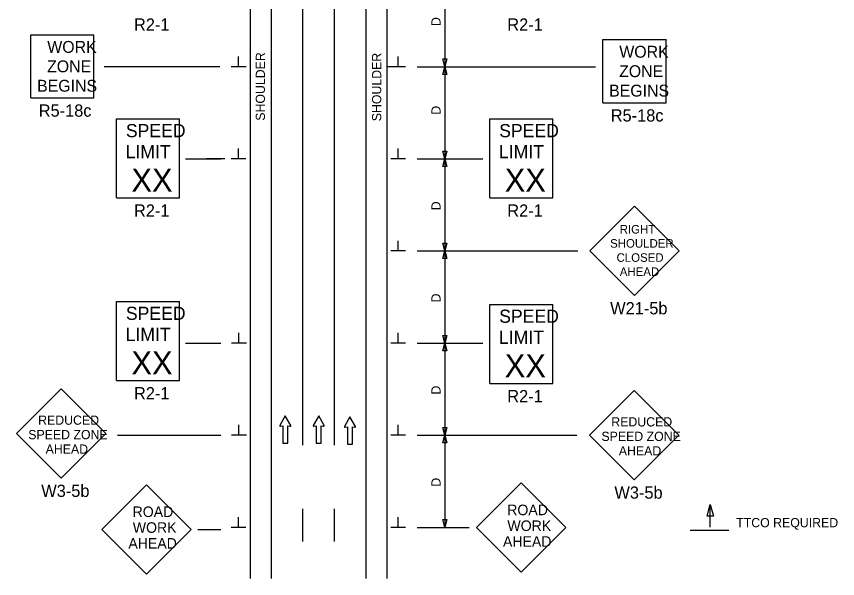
# Model space of a CAD drawing. Extents: x 16741 to 18479, y 6916 to 8211.
# Drawn here: x 16743 to 17367, y 7354 to 7781 of the extents above; entities that cross this region are included whole.
import ezdxf

# ---------------------------------------------------------------- set-up
doc = ezdxf.new("R2010")
doc.units = 0
for name, color, linetype in [('ALI_LEGAL_EX', 7, 'Continuous'), ('MT_SCRATCH_LEVEL_E', 7, 'Continuous'), ('PAVT_EDGE_EX', 7, 'Continuous'), ('TRAFFIC_SIGNS_PR', 7, 'Continuous'), ('TYPICAL_TEXT_DIMEN_PR', 7, 'Continuous')]:
    doc.layers.add(name, color=color, linetype=linetype)

msp = doc.modelspace()

# ---------------------------------------------------------------- linework, layer by layer
at = {"layer": 'ALI_LEGAL_EX'}
for p, q in [((16960.92, 8208.99), (16960.92, 7455.58)), ((16984.92, 8208.99), (16984.92, 7455.58))]:
    msp.add_line(p, q, dxfattribs=at)
for points in [[(16960.92, 7707.36), (16960.92, 7682.36)], [(16984.92, 7707.36), (16984.92, 7682.36)], [(16960.92, 7607.36), (16960.92, 7582.36)], [(16984.92, 7607.36), (16984.92, 7582.36)], [(16960.92, 7507.36), (16960.92, 7482.36)], [(16984.92, 7507.36), (16984.92, 7482.36)], [(16960.92, 7407.36), (16960.92, 7382.36)], [(16984.92, 7407.36), (16984.92, 7382.36)]]:
    msp.add_lwpolyline(points, dxfattribs=at)
at = {"layer": 'MT_SCRATCH_LEVEL_E'}
for p, q in [((16947.72, 7477.89), (16943.61, 7470.65)), ((16947.72, 7477.89), (16943.61, 7470.65)), ((16951.87, 7470.65), (16947.72, 7477.89)), ((16951.87, 7470.65), (16947.72, 7477.89)), ((16973.15, 7477.89), (16969.04, 7470.65)), ((16973.15, 7477.89), (16969.04, 7470.65)), ((16977.3, 7470.65), (16973.15, 7477.89)), ((16977.3, 7470.65), (16973.15, 7477.89)), ((16996.85, 7477.15), (16992.74, 7469.91)), ((16996.85, 7477.15), (16992.74, 7469.91)), ((17001, 7469.91), (16996.85, 7477.15)), ((17001, 7469.91), (16996.85, 7477.15)), ((16944.1, 7469.96), (16945.87, 7470.28)), ((16944.1, 7469.96), (16945.87, 7470.28)), ((16945.87, 7470.28), (16945.87, 7457.02)), ((16945.87, 7470.28), (16945.87, 7457.02)), ((16949.61, 7457.02), (16949.61, 7470.28)), ((16949.61, 7470.28), (16951.39, 7469.96)), ((16949.61, 7457.02), (16949.61, 7470.28)), ((16949.61, 7470.28), (16951.39, 7469.96)), ((16969.52, 7469.96), (16971.3, 7470.28)), ((16969.52, 7469.96), (16971.3, 7470.28)), ((16971.3, 7470.28), (16971.3, 7457.02)), ((16971.3, 7470.28), (16971.3, 7457.02)), ((16975.04, 7457.02), (16975.04, 7470.28)), ((16975.04, 7470.28), (16976.82, 7469.96)), ((16975.04, 7457.02), (16975.04, 7470.28)), ((16975.04, 7470.28), (16976.82, 7469.96)), ((16993.22, 7469.23), (16995, 7469.55)), ((16993.22, 7469.23), (16995, 7469.55)), ((16995, 7469.55), (16995, 7456.29)), ((16995, 7469.55), (16995, 7456.29)), ((16998.74, 7456.29), (16998.74, 7469.55)), ((16998.74, 7469.55), (17000.52, 7469.23)), ((16998.74, 7456.29), (16998.74, 7469.55)), ((16998.74, 7469.55), (17000.52, 7469.23)), ((16945.87, 7457.02), (16949.61, 7457.02)), ((16945.87, 7457.02), (16949.61, 7457.02)), ((16971.3, 7457.02), (16975.04, 7457.02)), ((16971.3, 7457.02), (16975.04, 7457.02)), ((16995, 7456.29), (16998.74, 7456.29)), ((16995, 7456.29), (16998.74, 7456.29))]:
    msp.add_line(p, q, dxfattribs=at)
for centre, start, end in [((16944.02, 7470.42), 150.42484, 279.96381), ((16944.02, 7470.42), 150.42484, 279.96381), ((16951.46, 7470.42), 260.03619, 29.77312), ((16951.46, 7470.42), 260.03619, 29.77312), ((16969.45, 7470.42), 150.42484, 279.96381), ((16969.45, 7470.42), 150.42484, 279.96381), ((16976.89, 7470.42), 260.03619, 29.77312), ((16976.89, 7470.42), 260.03619, 29.77312), ((16993.15, 7469.69), 150.42484, 279.96381), ((16993.15, 7469.69), 150.42484, 279.96381), ((17000.59, 7469.69), 260.03619, 29.77312), ((17000.59, 7469.69), 260.03619, 29.77312)]:
    msp.add_arc(centre, 0.463, start, end, dxfattribs=at)
at = {"layer": 'PAVT_EDGE_EX'}
for p, q in [((16920.92, 8208.99), (16920.92, 7354.26)), ((16936.92, 8208.99), (16936.92, 7354.26)), ((17008.92, 8208.99), (17008.92, 7354.26)), ((17024.92, 8208.99), (17024.92, 7354.26)), ((17028.22, 7743.18), (17024.92, 7743.18))]:
    msp.add_line(p, q, dxfattribs=at)
at = {"layer": 'TRAFFIC_SIGNS_PR'}
for p, q in [((16754.36, 7719.49), (16754.36, 7767.49)), ((16754.36, 7767.49), (16802.36, 7767.49)), ((16802.36, 7719.49), (16802.36, 7767.49)), ((17189.05, 7715.8), (17189.05, 7763.8)), ((17189.05, 7763.8), (17237.05, 7763.8)), ((17237.05, 7715.8), (17237.05, 7763.8)), ((16754.36, 7719.49), (16802.36, 7719.49)), ((17189.05, 7715.8), (17237.05, 7715.8)), ((16819.42, 7703.53), (16867.42, 7703.53)), ((16819.42, 7643.53), (16819.42, 7703.53)), ((16867.42, 7643.53), (16867.42, 7703.53)), ((17103.1, 7703.53), (17151.1, 7703.53)), ((17103.1, 7643.53), (17103.1, 7703.53)), ((17151.1, 7643.53), (17151.1, 7703.53)), ((16819.42, 7643.53), (16867.42, 7643.53)), ((17103.1, 7643.53), (17151.1, 7643.53)), ((17213.17, 7637.2), (17179.23, 7603.26)), ((17247.11, 7603.26), (17213.17, 7637.2)), ((17179.23, 7603.26), (17213.17, 7569.31)), ((17213.17, 7569.31), (17247.11, 7603.26)), ((16819.42, 7564.71), (16867.42, 7564.71)), ((16819.42, 7504.71), (16819.42, 7564.71)), ((16867.42, 7504.71), (16867.42, 7564.71)), ((17103.1, 7562.52), (17151.1, 7562.52)), ((17103.1, 7502.52), (17103.1, 7562.52)), ((17151.1, 7502.52), (17151.1, 7562.52)), ((16819.42, 7504.71), (16867.42, 7504.71)), ((17103.1, 7502.52), (17151.1, 7502.52)), ((16777.36, 7498.45), (16743.42, 7464.51)), ((16811.3, 7464.51), (16777.36, 7498.45)), ((17212.9, 7497.14), (17178.96, 7463.2)), ((17246.84, 7463.2), (17212.9, 7497.14)), ((16743.42, 7464.51), (16777.36, 7430.57)), ((16777.36, 7430.57), (16811.3, 7464.51)), ((17178.96, 7463.2), (17212.9, 7429.26)), ((17212.9, 7429.26), (17246.84, 7463.2)), ((17126.96, 7426.95), (17093.02, 7393.01)), ((17160.9, 7393.01), (17126.96, 7426.95)), ((16842.28, 7425.55), (16808.34, 7391.61)), ((16876.22, 7391.61), (16842.28, 7425.55)), ((16808.34, 7391.61), (16842.28, 7357.67)), ((16842.28, 7357.67), (16876.22, 7391.61)), ((17093.02, 7393.01), (17126.96, 7359.07)), ((17126.96, 7359.07), (17160.9, 7393.01))]:
    msp.add_line(p, q, dxfattribs=at)
at = {"layer": 'TYPICAL_TEXT_DIMEN_PR'}
for p, q in [((17068.92, 7813.18), (17068.92, 7743.18)), ((16912.29, 7743.18), (16912.29, 7750.97)), ((17033.54, 7743.18), (17033.54, 7750.97)), ((17068.92, 7743.18), (17067.35, 7749.04)), ((17067.35, 7749.04), (17068.92, 7749.04)), ((17068.92, 7743.18), (17067.35, 7749.04)), ((17067.35, 7749.04), (17068.92, 7749.04)), ((17068.92, 7749.04), (17070.49, 7749.04)), ((17070.49, 7749.04), (17068.92, 7743.18)), ((17068.92, 7749.04), (17070.49, 7749.04)), ((17070.49, 7749.04), (17068.92, 7743.18)), ((16897.92, 7743.18), (16810.2, 7743.18)), ((16912.29, 7743.18), (16906.67, 7743.18)), ((16917.92, 7743.18), (16912.29, 7743.18)), ((17033.54, 7743.18), (17027.92, 7743.18)), ((17039.17, 7743.18), (17033.54, 7743.18)), ((17047.92, 7743.18), (17183.51, 7743.18)), ((17067.35, 7737.32), (17068.92, 7743.18)), ((17068.92, 7743.18), (17068.92, 7673.18)), ((17068.92, 7743.18), (17070.49, 7737.32)), ((17068.92, 7737.32), (17067.35, 7737.32)), ((17070.49, 7737.32), (17068.92, 7737.32)), ((16912.13, 7673.18), (16912.13, 7680.97)), ((17033.54, 7673.18), (17033.54, 7680.97)), ((17068.92, 7673.18), (17067.35, 7679.04)), ((17067.35, 7679.04), (17068.92, 7679.04)), ((17068.92, 7679.04), (17070.49, 7679.04)), ((17070.49, 7679.04), (17068.92, 7673.18)), ((16871.92, 7673.18), (16898.82, 7673.18)), ((16901.7, 7673.14), (16887.9, 7673.14)), ((16912.13, 7673.18), (16906.51, 7673.18)), ((16917.76, 7673.18), (16912.13, 7673.18)), ((17033.54, 7673.18), (17027.92, 7673.18)), ((17039.17, 7673.18), (17033.54, 7673.18)), ((17047.92, 7673.18), (17097.97, 7673.18)), ((17067.35, 7667.32), (17068.92, 7673.18)), ((17068.92, 7673.18), (17068.92, 7603.18)), ((17068.92, 7673.18), (17070.49, 7667.32)), ((17068.92, 7667.32), (17067.35, 7667.32)), ((17070.49, 7667.32), (17068.92, 7667.32)), ((17033.54, 7603.18), (17033.54, 7610.97)), ((17068.92, 7603.18), (17067.35, 7609.04)), ((17067.35, 7609.04), (17068.92, 7609.04)), ((17068.92, 7609.04), (17070.49, 7609.04)), ((17070.49, 7609.04), (17068.92, 7603.18)), ((17033.54, 7603.18), (17027.92, 7603.18)), ((17039.17, 7603.18), (17033.54, 7603.18)), ((17047.92, 7603.18), (17169.97, 7603.18)), ((17067.35, 7597.32), (17068.92, 7603.18)), ((17068.92, 7603.18), (17068.92, 7533.18)), ((17068.92, 7603.18), (17070.49, 7597.32)), ((17068.92, 7597.32), (17067.35, 7597.32)), ((17070.49, 7597.32), (17068.92, 7597.32)), ((16912.52, 7533.18), (16912.52, 7540.97)), ((17033.54, 7533.18), (17033.54, 7540.97)), ((17068.92, 7533.18), (17067.35, 7539.04)), ((17067.35, 7539.04), (17068.92, 7539.04)), ((17068.92, 7539.04), (17070.49, 7539.04)), ((17070.49, 7539.04), (17068.92, 7533.18)), ((16871.92, 7533.18), (16898.82, 7533.18)), ((16912.52, 7533.18), (16906.89, 7533.18)), ((16918.14, 7533.18), (16912.52, 7533.18)), ((17033.54, 7533.18), (17027.92, 7533.18)), ((17039.17, 7533.18), (17033.54, 7533.18)), ((17047.92, 7533.18), (17097.97, 7533.18)), ((17067.35, 7527.32), (17068.92, 7533.18)), ((17068.92, 7533.18), (17068.92, 7463.18)), ((17068.92, 7533.18), (17070.49, 7527.32)), ((17068.92, 7527.32), (17067.35, 7527.32)), ((17070.49, 7527.32), (17068.92, 7527.32)), ((16912.52, 7463.18), (16912.52, 7470.97)), ((17033.54, 7463.18), (17033.54, 7470.97)), ((16820.27, 7463.18), (16898.82, 7463.18)), ((16912.52, 7463.18), (16906.89, 7463.18)), ((16918.14, 7463.18), (16912.52, 7463.18)), ((17033.54, 7463.18), (17027.92, 7463.18)), ((17039.17, 7463.18), (17033.54, 7463.18)), ((17047.92, 7463.18), (17169.32, 7463.18)), ((17068.92, 7463.18), (17067.35, 7469.04)), ((17067.35, 7469.04), (17068.92, 7469.04)), ((17067.35, 7457.32), (17068.92, 7463.18)), ((17068.92, 7469.04), (17070.49, 7469.04)), ((17070.49, 7469.04), (17068.92, 7463.18)), ((17068.92, 7463.18), (17068.92, 7393.18)), ((17068.92, 7463.18), (17070.49, 7457.32)), ((17068.92, 7457.32), (17067.35, 7457.32)), ((17070.49, 7457.32), (17068.92, 7457.32)), ((17268.34, 7401.67), (17270.69, 7410.46)), ((17270.69, 7393.34), (17270.69, 7410.46)), ((17270.69, 7410.46), (17273.05, 7401.67)), ((16912.22, 7393.18), (16912.22, 7400.97)), ((17033.54, 7393.18), (17033.54, 7400.97)), ((17270.69, 7401.67), (17268.34, 7401.67)), ((17273.05, 7401.67), (17270.69, 7401.67)), ((17068.92, 7393.18), (17067.35, 7399.04)), ((17067.35, 7399.04), (17068.92, 7399.04)), ((17068.92, 7399.04), (17070.49, 7399.04)), ((17070.49, 7399.04), (17068.92, 7393.18)), ((16881.24, 7391.57), (16898.82, 7391.57)), ((16912.22, 7393.18), (16906.6, 7393.18)), ((16917.85, 7393.18), (16912.22, 7393.18)), ((17033.54, 7393.18), (17027.92, 7393.18)), ((17039.17, 7393.18), (17033.54, 7393.18)), ((17047.92, 7393.18), (17087.38, 7393.18)), ((17284.87, 7390.84), (17255.43, 7390.84))]:
    msp.add_line(p, q, dxfattribs=at)

# ---------------------------------------------------------------- texts
at = {"layer": 'TRAFFIC_SIGNS_PR'}
for s, height, p in [('R2-1', 9.3, (16832.76, 7770.56)), ('R2-1', 9.3, (17116.44, 7770.56)), ('WORK', 9.021, (16766.86, 7753.7)), ('WORK', 9.021, (17201.55, 7750.01)), ('ZONE', 9.021, (16766.71, 7738.94)), ('ZONE', 9.021, (17201.4, 7735.24)), ('BEGINS', 9.021, (16759.12, 7724.18)), ('BEGINS', 9.021, (17193.81, 7720.48)), ('R5-18c', 9.3, (16760.38, 7705.19)), ('R5-18c', 9.3, (17195.06, 7701.5)), ('SPEED', 10, (16826.62, 7689.61)), ('SPEED', 10, (17110.3, 7689.61)), ('LIMIT', 10, (16826.42, 7673.61)), ('LIMIT', 10, (17110.1, 7673.61)), ('XX', 17.538, (16830.81, 7648.23)), ('XX', 17.538, (17114.49, 7648.23)), ('R2-1', 9.3, (16832.76, 7629.24)), ('R2-1', 9.3, (17116.44, 7629.24)), ('RIGHT', 6.5, (17201.84, 7616.42)), ('SHOULDER', 6.5, (17194.57, 7605.67)), ('CLOSED', 6.5, (17199.46, 7594.92)), ('AHEAD', 6.5, (17201.91, 7584.17)), ('W21-5b', 9.3, (17194.61, 7555.01)), ('SPEED', 10, (16826.62, 7550.79)), ('SPEED', 10, (17110.3, 7548.6)), ('LIMIT', 10, (16826.42, 7534.79)), ('LIMIT', 10, (17110.1, 7532.6)), ('XX', 17.538, (16830.81, 7509.41)), ('XX', 17.538, (17114.49, 7507.22)), ('R2-1', 9.3, (16832.76, 7490.42)), ('R2-1', 9.3, (17116.44, 7488.22)), ('REDUCED', 7, (16759.93, 7471.14)), ('REDUCED', 7, (17195.47, 7469.83)), ('SPEED ZONE', 7, (16752.42, 7460.14)), ('SPEED ZONE', 7, (17187.97, 7458.83)), ('AHEAD', 7, (16765.62, 7449.14)), ('AHEAD', 7, (17201.17, 7447.83)), ('W3-5b', 9.3, (16762.3, 7416.27)), ('W3-5b', 9.3, (17197.84, 7414.96)), ('ROAD', 8, (16831.71, 7401.03)), ('ROAD', 8, (17116.39, 7402.43)), ('WORK', 8, (16831.84, 7389.03)), ('WORK', 8, (17116.53, 7390.43)), ('AHEAD', 8, (16828.48, 7377.03)), ('AHEAD', 8, (17113.16, 7378.43))]:
    msp.add_text(s, height=height, dxfattribs=at).set_placement(p)
at = {"layer": 'TYPICAL_TEXT_DIMEN_PR'}
for s, p in [('D', (17065.73, 7774.07)), ('SHOULDER', (16932.28, 7702.13)), ('SHOULDER', (17020.66, 7701.73)), ('D', (17065.73, 7706.71)), ('D', (17065.73, 7634.07)), ('D', (17065.73, 7564.07)), ('D', (17065.73, 7494.07)), ('D', (17065.73, 7424.07))]:
    msp.add_text(s, height=7, rotation=90, dxfattribs=at).set_placement(p)
msp.add_text('TTCO REQUIRED', height=7, dxfattribs=at).set_placement((17290.39, 7393.26))

doc.saveas('drawing.dxf')
